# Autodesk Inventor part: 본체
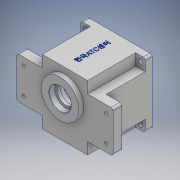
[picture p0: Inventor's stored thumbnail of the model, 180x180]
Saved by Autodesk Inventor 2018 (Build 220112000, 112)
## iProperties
Created: 2020-07
Part Number: 본체
Material: 알루미늄 6061
Document SubType Name: Modeling
Designer: Admin
Density: 2.7 g/cm^3
Appearance: 알루미늄 - 평지
Mass: 876.351 g
Surface Area: 793.93 cm^2
Volume: 324.574 cm^3
Author: Admin
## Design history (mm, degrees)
sketch "스케치1"
  geometry: L1 (47, -47)-(-47, -47); L2 (-47, -47)-(-47, 47); L3 (-47, 47)-(47, 47); L4 (47, 47)-(47, -47); L5 (47, -47)-(-47, 47); L6 (-47, -47)-(47, 47); 1 further point
  constraints: 12 end point, 2 midpoint, 2 parallel, 1 horizontal, 1 perpendicular
  dimensions: "d0" = 94 distance of L2.end L3.end; "d1" = 94 distance of L1.end L2.end
extrude "돌출1" new body sketch "스케치1" distance "d2" = 80; taper "d3" = 0 deg
sketch "스케치2"
  geometry: L1 (-47, 47)-(-47, -47) reference; L2 (-47, 47)-(-33, 47); L3 (-33, 47)-(-33, 30); L4 (-33, 30)-(-47, 30); L5 (-47, 30)-(-47, 47); L6 (-65.8, 0)-(65.8, 0) reference; L7 (0, -65.8)-(0, 65.8) reference; L8 (47, 47)-(33, 47); L9 (33, 47)-(33, 30); L10 (33, 30)-(47, 30); L11 (47, 30)-(47, 47); L12 (-47, -47)-(-33, -47); L13 (-33, -47)-(-33, -30); L14 (-33, -30)-(-47, -30); L15 (-47, -30)-(-47, -47); L16 (47, -47)-(33, -47); L17 (33, -47)-(33, -30); L18 (33, -30)-(47, -30); L19 (47, -30)-(47, -47); 1 further point
  constraints: 32 end point, 11 symmetric about line, 2 parallel, 1 horizontal, 1 perpendicular
  dimensions: "d4" = 33 distance from line of point (0, 0) L3; "d5" = 30 distance from line of point (0, 0) L4
extrude "돌출2" cut sketch "스케치2" distance "d6" = 70; taper "d7" = 0 deg
sketch "스케치3"
  geometry: L1 (-70, 30)-(70, 30); L2 (70, 30)-(70, -30); L3 (70, -30)-(-70, -30); L4 (-70, -30)-(-70, 30); 1 further point
  constraints: 8 end point, 2 parallel, 1 horizontal, 1 perpendicular
  dimensions: "d8" = 140 distance of L1.start L1.end; "d9" = 60 distance of L1.end L2.end; "d10" = 30 distance from line of L1 point (0, 0); "d11" = 70 distance from line of point (0, 0) L4
extrude "돌출3" join sketch "스케치3" distance "d12" = 13; taper "d13" = 0 deg
sketch "스케치4"
  geometry: L1 (0, -65.8)-(0, 65.8) reference; C1 r 27.5 at (0, 11); 1 further point
  constraints: 1 centre point, 1 point on line
  dimensions: "d14" = 55 diameter of C1; "d15" = 11 distance of point (0, 0) C1.centre
extrude "돌출4" join sketch "스케치4" distance "d16" = 7; taper "d17" = 0 deg
sketch "스케치5"
  geometry: C1 r 43 at (0, 0); 1 further point
  constraints: 1 centre point, 1 coincident
  dimensions: "d18" = 86 diameter of C1
extrude "돌출5" cut sketch "스케치5" distance "d19" = 9; taper "d20" = 0 deg
sketch "스케치6"
  geometry: C1 r 40 at (0, 0); 1 further point
  constraints: 1 centre point, 1 coincident
  dimensions: "d21" = 80 diameter of C1
extrude "돌출6" cut sketch "스케치6" distance "d26" = 62; taper "d27" = 0 deg
sketch "스케치7"
  geometry: L1 (0, 65.8)-(0, -65.8) reference; A1 r 21 centre (0, -11) between (-8.978, 7.984) and (8.978, 7.984); A2 r 15 centre (0, 20) between (8.978, 7.984) and (-8.978, 7.984); 1 further point
  constraints: 4 point on circle, 2 centre point, 2 point on line
  dimensions: "d28" = 42 diameter of A1; "d29" = 30 diameter of A2; "d30" = 11 distance of point (0, 0) A1.centre; "d31" = 20 distance of A2.centre point (0, 0)
extrude "돌출7" join sketch "스케치7" distance "d34" = 7; taper "d35" = 0 deg
sketch "스케치15"
  geometry: C1 r 17.5 at (0, -11); A1 r 21 centre (0, -11) between (-8.978, 7.984) and (8.978, 7.984) reference; 1 further point
  constraints: 1 centre point, 1 coincident
  dimensions: "d55" = 35 diameter of C1
extrude "돌출14" cut sketch "스케치15" distance "d56" = 10; taper "d57" = 0 deg
sketch "스케치16"
  geometry: C1 r 11 at (0, 20); A1 r 15 centre (0, 20) between (8.978, 7.984) and (-8.978, 7.984) reference; 1 further point
  constraints: 1 centre point, 1 coincident
  dimensions: "d58" = 22 diameter of C1
extrude "돌출15" cut sketch "스케치16" distance "d59" = 7; taper "d60" = 0 deg
sketch "스케치17"
  geometry: C1 r 17.5 at (0, 0) reference; C2 r 12.5 at (0, 0); 1 further point
  constraints: 1 centre point, 1 coincident
  dimensions: "d61" = 25 diameter of C2
extrude "돌출16" cut sketch "스케치17" distance "d62" = 4.7; taper "d63" = 0 deg
sketch "스케치18"
  geometry: C1 r 9.5 at (0, 0); A1 r 15 centre (0, 0) between (8.978, -12.016) and (-8.978, -12.016) reference; 1 further point
  constraints: 1 centre point, 1 coincident
  dimensions: "d64" = 19 diameter of C1
extrude "돌출17" cut sketch "스케치18" distance "d65" = 3; taper "d66" = 0 deg
sketch "스케치19"
  geometry: C1 r 12.5 at (0, 0) reference; C2 r 16 at (0, 0); 1 further point
  constraints: 1 centre point, 1 coincident
  dimensions: "d67" = 32 diameter of C2
extrude "돌출18" cut sketch "스케치19" distance "d68" = 8.3; taper "d69" = 0 deg
sketch "스케치20"
  geometry: L1 (-78.7, 27)-(-87, 27) reference; L2 (-86.2, 27)-(-87, 27.462); L3 (-87, 38.5)-(-87, -16.5) reference; L4 (-86.2, 27)-(-86.2, 11); L5 (-86.2, 11)-(-87, 11); L6 (-87, 27.462)-(-87, 11); L7 (-100.841, 11)-(-44.174, 11); 1 further point
  constraints: 10 end point, 2 point on line, 1 collinear, 1 horizontal, 1 midpoint, 1 perpendicular, 1 vertical
  dimensions: "d70" = 16 distance between parallel lines of L7 L1; "d71" = 0 distance between parallel lines of L5 L7; "d72" = 0.8 distance between parallel lines of L3 L4; "d73" = 30 deg angle of L2 L1
revolve "회전1" sketch "스케치20" stored, may be unused: angle "d74" = 90 deg
sketch "스케치21"
  geometry: L1 (-98, 0)-(98, 0) reference; L2 (0, -65.8)-(0, 65.8) reference; C1 r 2.25 at (-60, 19); C2 r 2.25 at (-60, -19); C3 r 2.25 at (60, 19); C4 r 2.25 at (60, -19); 1 further point
  constraints: 4 centre point, 3 symmetric about line, 3 other
  dimensions: "d75" = 4.5 diameter of C1; "d76" = 19 distance from line of C1.centre L1; "d77" = 60 horizontal distance of point (0, 0) C1.centre
extrude "돌출19" cut sketch "스케치21" stored distance "d78" = 0; taper "d79" = 0 deg
sketch "스케치22"
  geometry: L1 (-98, 0)-(98, 0) reference; L2 (0, 65.8)-(0, -65.8) reference; C1 r 2.25 at (60, 19) reference; C2 r 5 at (60, 19); C3 r 5 at (60, -19); C4 r 5 at (-60, 19); C5 r 5 at (-60, -19); 1 further point
  constraints: 4 centre point, 3 symmetric about line, 1 coincident, 3 other
  dimensions: "d80" = 10 diameter of C2
extrude "돌출20" cut sketch "스케치22" distance "d81" = 5; taper "d82" = 0 deg
sketch "스케치23"
  geometry: L1 (-98, 0)-(98, 0) reference; L2 (0, 65.8)-(0, -65.8) reference; C1 r 3.5 at (40, 40); C2 r 3.5 at (40, -40); C3 r 3.5 at (-40, 40); C4 r 3.5 at (-40, -40); 1 further point
  constraints: 4 centre point, 3 symmetric about line, 3 other
  dimensions: "d83" = 7 diameter of C1; "d84" = 40 horizontal distance of point (0, 0) C1.centre; "d85" = 40 horizontal distance of point (0, 0) C1.centre
extrude "돌출21" cut sketch "스케치23" stored distance "d86" = 0; taper "d87" = 0 deg
sketch "스케치24"
  geometry: L1 (-39.799, -4)-(-40, -4); L2 (0, 65.8)-(0, -65.8) reference; L3 (39.799, -4)-(40, -4); A1 r 4 centre (-36, 0) between (-36.19, -3.995) and (-36, -4); A2 r 4 centre (-36, 0) between (-35.995, 4) and (-36.19, 3.995); A3 r 4 centre (-36, 0) between (-36, -4) and (-35.995, 4); A4 r 40 centre (0, 0) between (-37.81, 13.054) and (-39.279, 7.559); A5 r 40 centre (0, 0) between (-39.279, -7.559) and (-37.644, -13.526); A6 r 3 centre (-36.333, 6.992) between (-39.279, 7.559) and (-36.19, 3.995); A7 r 3 centre (-36.333, -6.992) between (-36.19, -3.995) and (-39.279, -7.559); A8 r 40 centre (0, 0) between (39.279, 7.559) and (37.81, 13.054); A9 r 4 centre (36, 0) between (36.19, 3.995) and (35.995, 4); A10 r 3 centre (36.333, 6.992) between (36.19, 3.995) and (39.279, 7.559); A11 r 4 centre (36, 0) between (35.995, 4) and (36, -4); A12 r 4 centre (36, 0) between (36, -4) and (36.19, -3.995); A13 r 3 centre (36.333, -6.992) between (39.279, -7.559) and (36.19, -3.995); A14 r 40 centre (0, 0) between (37.644, -13.526) and (39.279, -7.559); A15 r 40 centre (0, 0) between (-39.279, 7.559) and (-39.279, -7.559); A16 r 40 centre (0, 0) between (39.279, -7.559) and (39.279, 7.559); 2 further points
  constraints: 36 point on circle, 16 centre point, 13 symmetric about line, 6 tangent, 5 coincident, 4 end point, 1 equal radius, 1 horizontal, 17 other
  dimensions: "d89" = 36 distance of point (0, 0) A1.centre; "d90" = 0 vertical distance of A1.centre point (0, 0); "d91" = 4 radius of A3; "d92" = 3 radius of A6 (derived)
extrude "돌출22" join sketch "스케치24" stored distance "d93" = 5; taper "d94" = 0 deg
sketch "스케치25"
  geometry: A1 r 4 centre (-36, 0) between (-36.19, -3.995) and (-36.19, 3.995) reference; A2 r 4 centre (36, 0) between (36.19, 3.995) and (36.19, -3.995) reference; 3 further points
  constraints: 2 coincident
hole "구멍1" sketch "스케치25" at (-36, 0), (36, 0) diameter "d95" = 3.242; stored, may be unused: countersink angle "d99" = 90 deg, drill point angle "d101" = 118 deg; dims "d96" = 7, "d97" = 4, "d98" = 2, "d100" = 9
fillet "모깎기1" dims "d102" = 3
chamfer "모따기1" distance "d103" = 1; stored, may be unused: second distance "d104" = 2, angle "d105" = 45 deg
sketch "스케치26"
  geometry: L1 (77, 80)-(-11, 80) reference; L2 (33, -24.4)-(33, 97.4) reference; 2 further points
  constraints: 1 other
  dimensions: "d106" = 40 distance from line of L1 point (33, 40); "d107" = 0 distance from line of L2 point (33, 40)
feature "엠보싱1" sketch "스케치26" dims "d0" = 94, "d1" = 94, "d4" = 33, "d5" = 30, "d108" = 0.5, "d109" = 0
node "솔리드1"
